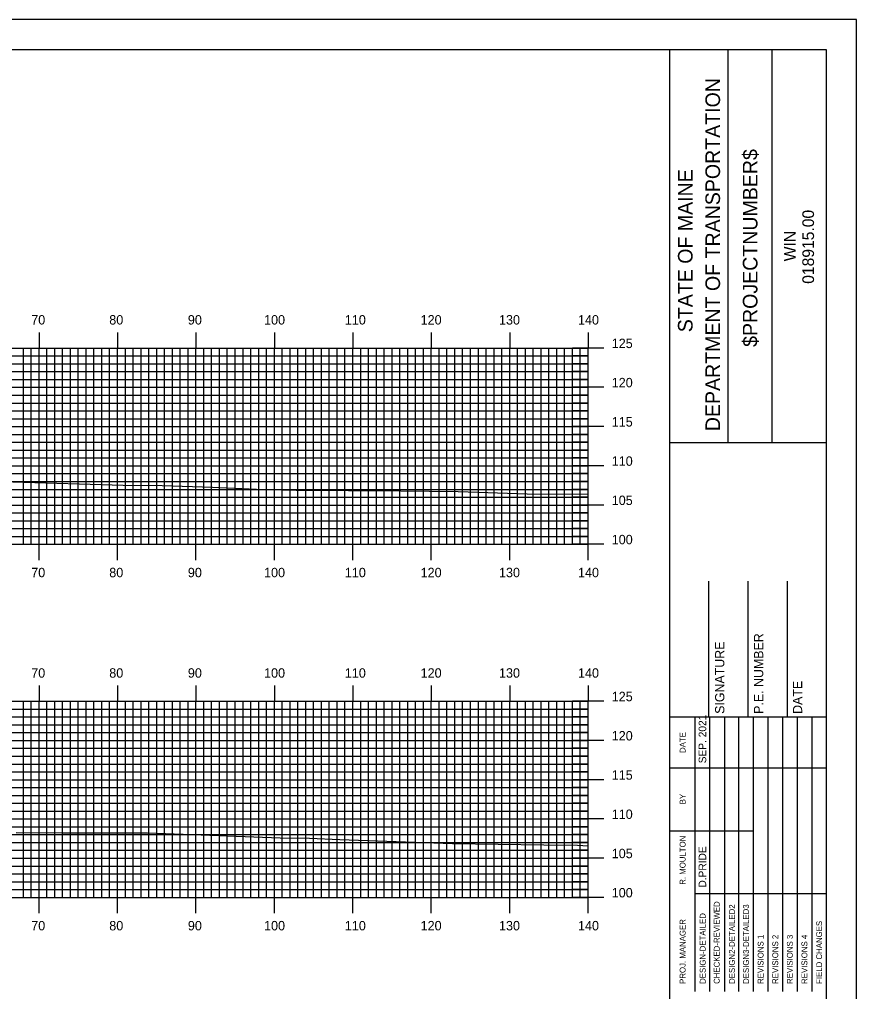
# Model space of a CAD drawing. Extents: x 1772809 to 1773153, y 442591 to 442811.
# Drawn here: x 1773042.6 to 1773149.3, y 442686.7 to 442810.5 of the extents above; entities that cross this region are included whole.
import ezdxf

# ---------------------------------------------------------------- set-up
doc = ezdxf.new("R2010")
doc.units = 0
for name, color, linetype in [('BORDER', 7, 'Continuous'), ('H_V ANNOTATION', 7, 'Continuous'), ('MAJOR', 7, 'Continuous'), ('MINOR', 7, 'Continuous'), ('PLOT BOUNDARY', 7, 'Continuous'), ('S_Roadway_Centerline', 7, 'Continuous')]:
    doc.layers.add(name, color=color, linetype=linetype)

msp = doc.modelspace()

# ---------------------------------------------------------------- linework, layer by layer
at = {"layer": 'BORDER'}
for p, q in [((1773125.52, 442596.67), (1773125.52, 442806.67)), ((1773132.98, 442756.66), (1773132.98, 442806.66)), ((1773138.57, 442756.66), (1773138.57, 442806.66)), ((1773125.52, 442756.65), (1773145.52, 442756.65)), ((1773130.52, 442721.67), (1773130.52, 442738.97)), ((1773135.52, 442721.67), (1773135.52, 442738.97)), ((1773140.52, 442721.67), (1773140.52, 442738.97)), ((1773125.52, 442721.67), (1773145.52, 442721.67))]:
    msp.add_line(p, q, dxfattribs=at)
msp.add_lwpolyline([(1772825.52, 442596.67), (1773145.52, 442596.67), (1773145.52, 442806.67), (1772825.52, 442806.67)], close=True, dxfattribs=at)
for points in [[(1773128.75, 442715.17), (1773128.75, 442721.67)], [(1773130.61, 442686.68), (1773130.61, 442721.67)], [(1773132.48, 442721.67), (1773132.48, 442686.68)], [(1773134.34, 442686.68), (1773134.34, 442721.67)], [(1773136.2, 442686.68), (1773136.2, 442721.67)], [(1773138.07, 442686.68), (1773138.07, 442721.67)], [(1773139.93, 442686.68), (1773139.93, 442721.67)], [(1773141.79, 442686.68), (1773141.79, 442721.67)], [(1773143.66, 442686.68), (1773143.66, 442721.67)], [(1773128.75, 442686.68), (1773128.75, 442720.26)], [(1773125.52, 442715.17), (1773145.52, 442715.17)], [(1773125.52, 442707.17), (1773128.75, 442707.17)], [(1773128.75, 442707.17), (1773136.2, 442707.17)], [(1773128.75, 442699.17), (1773145.52, 442699.17)]]:
    msp.add_lwpolyline(points, dxfattribs=at)
at = {"layer": 'MAJOR'}
for p, q in [((1773045.12, 442770.67), (1773045.12, 442768.67)), ((1773055.12, 442770.67), (1773055.12, 442768.67)), ((1773065.12, 442770.67), (1773065.12, 442768.67)), ((1773075.12, 442770.67), (1773075.12, 442768.67)), ((1773085.12, 442770.67), (1773085.12, 442768.67)), ((1773095.12, 442770.67), (1773095.12, 442768.67)), ((1773105.12, 442770.67), (1773105.12, 442768.67)), ((1773115.12, 442770.67), (1773115.12, 442768.67)), ((1772835.12, 442768.67), (1773115.12, 442768.67)), ((1772835.12, 442768.67), (1773115.12, 442768.67)), ((1773045.12, 442743.67), (1773045.12, 442768.67)), ((1773055.12, 442743.67), (1773055.12, 442768.67)), ((1773065.12, 442743.67), (1773065.12, 442768.67)), ((1773075.12, 442743.67), (1773075.12, 442768.67)), ((1773085.12, 442743.67), (1773085.12, 442768.67)), ((1773095.12, 442743.67), (1773095.12, 442768.67)), ((1773105.12, 442743.67), (1773105.12, 442768.67)), ((1773117.12, 442768.67), (1773113.12, 442768.67)), ((1773115.12, 442743.67), (1773115.12, 442768.67)), ((1773115.12, 442743.67), (1773115.12, 442768.67)), ((1772835.12, 442763.67), (1773115.12, 442763.67)), ((1773117.12, 442763.67), (1773113.12, 442763.67)), ((1772835.12, 442758.67), (1773115.12, 442758.67)), ((1773117.12, 442758.67), (1773113.12, 442758.67)), ((1772835.12, 442753.67), (1773115.12, 442753.67)), ((1773117.12, 442753.67), (1773113.12, 442753.67)), ((1772835.12, 442748.67), (1773115.12, 442748.67)), ((1773117.12, 442748.67), (1773113.12, 442748.67)), ((1772835.12, 442743.67), (1773115.12, 442743.67)), ((1772835.12, 442743.67), (1773115.12, 442743.67)), ((1773045.12, 442741.66), (1773045.12, 442743.67)), ((1773055.12, 442741.66), (1773055.12, 442743.67)), ((1773065.12, 442741.66), (1773065.12, 442743.67)), ((1773075.12, 442741.66), (1773075.12, 442743.67)), ((1773085.12, 442741.66), (1773085.12, 442743.67)), ((1773095.12, 442741.66), (1773095.12, 442743.67)), ((1773105.12, 442741.66), (1773105.12, 442743.67)), ((1773117.12, 442743.67), (1773113.12, 442743.67)), ((1773115.12, 442741.66), (1773115.12, 442743.67)), ((1773045.12, 442725.67), (1773045.12, 442723.67)), ((1773055.12, 442725.67), (1773055.12, 442723.67)), ((1773065.12, 442725.67), (1773065.12, 442723.67)), ((1773075.12, 442725.67), (1773075.12, 442723.67)), ((1773085.12, 442725.67), (1773085.12, 442723.67)), ((1773095.12, 442725.67), (1773095.12, 442723.67)), ((1773105.12, 442725.67), (1773105.12, 442723.67)), ((1773115.12, 442725.67), (1773115.12, 442723.67)), ((1772835.12, 442723.67), (1773115.12, 442723.67)), ((1772835.12, 442723.67), (1773115.12, 442723.67)), ((1773045.12, 442698.67), (1773045.12, 442723.67)), ((1773055.12, 442698.67), (1773055.12, 442723.67)), ((1773065.12, 442698.67), (1773065.12, 442723.67)), ((1773075.12, 442698.67), (1773075.12, 442723.67)), ((1773085.12, 442698.67), (1773085.12, 442723.67)), ((1773095.12, 442698.67), (1773095.12, 442723.67)), ((1773105.12, 442698.67), (1773105.12, 442723.67)), ((1773117.12, 442723.67), (1773113.12, 442723.67)), ((1773115.12, 442698.67), (1773115.12, 442723.67)), ((1773115.12, 442698.67), (1773115.12, 442723.67)), ((1772835.12, 442718.67), (1773115.12, 442718.67)), ((1773117.12, 442718.67), (1773113.12, 442718.67)), ((1772835.12, 442713.67), (1773115.12, 442713.67)), ((1773117.12, 442713.67), (1773113.12, 442713.67)), ((1772835.12, 442708.67), (1773115.12, 442708.67)), ((1773117.12, 442708.67), (1773113.12, 442708.67)), ((1772835.12, 442703.67), (1773115.12, 442703.67)), ((1773117.12, 442703.67), (1773113.12, 442703.67)), ((1772835.12, 442698.67), (1773115.12, 442698.67)), ((1772835.12, 442698.67), (1773115.12, 442698.67)), ((1773045.12, 442696.66), (1773045.12, 442698.67)), ((1773055.12, 442696.66), (1773055.12, 442698.67)), ((1773065.12, 442696.66), (1773065.12, 442698.67)), ((1773075.12, 442696.66), (1773075.12, 442698.67)), ((1773085.12, 442696.66), (1773085.12, 442698.67)), ((1773095.12, 442696.66), (1773095.12, 442698.67)), ((1773105.12, 442696.66), (1773105.12, 442698.67)), ((1773117.12, 442698.67), (1773113.12, 442698.67)), ((1773115.12, 442696.66), (1773115.12, 442698.67))]:
    msp.add_line(p, q, dxfattribs=at)
at = {"layer": 'MINOR'}
for p, q in [((1773043.12, 442743.67), (1773043.12, 442768.67)), ((1773044.12, 442743.67), (1773044.12, 442768.67)), ((1773046.12, 442743.67), (1773046.12, 442768.67)), ((1773047.12, 442743.67), (1773047.12, 442768.67)), ((1773048.12, 442743.67), (1773048.12, 442768.67)), ((1773049.12, 442743.67), (1773049.12, 442768.67)), ((1773050.12, 442743.67), (1773050.12, 442768.67)), ((1773051.12, 442743.67), (1773051.12, 442768.67)), ((1773052.12, 442743.67), (1773052.12, 442768.67)), ((1773053.12, 442743.67), (1773053.12, 442768.67)), ((1773054.12, 442743.67), (1773054.12, 442768.67)), ((1773056.12, 442743.67), (1773056.12, 442768.67)), ((1773057.12, 442743.67), (1773057.12, 442768.67)), ((1773058.12, 442743.67), (1773058.12, 442768.67)), ((1773059.12, 442743.67), (1773059.12, 442768.67)), ((1773060.12, 442743.67), (1773060.12, 442768.67)), ((1773061.12, 442743.67), (1773061.12, 442768.67)), ((1773062.12, 442743.67), (1773062.12, 442768.67)), ((1773063.12, 442743.67), (1773063.12, 442768.67)), ((1773064.12, 442743.67), (1773064.12, 442768.67)), ((1773066.12, 442743.67), (1773066.12, 442768.67)), ((1773067.12, 442743.67), (1773067.12, 442768.67)), ((1773068.12, 442743.67), (1773068.12, 442768.67)), ((1773069.12, 442743.67), (1773069.12, 442768.67)), ((1773070.12, 442743.67), (1773070.12, 442768.67)), ((1773071.12, 442743.67), (1773071.12, 442768.67)), ((1773072.12, 442743.67), (1773072.12, 442768.67)), ((1773073.12, 442743.67), (1773073.12, 442768.67)), ((1773074.12, 442743.67), (1773074.12, 442768.67)), ((1773076.12, 442743.67), (1773076.12, 442768.67)), ((1773077.12, 442743.67), (1773077.12, 442768.67)), ((1773078.12, 442743.67), (1773078.12, 442768.67)), ((1773079.12, 442743.67), (1773079.12, 442768.67)), ((1773080.12, 442743.67), (1773080.12, 442768.67)), ((1773081.12, 442743.67), (1773081.12, 442768.67)), ((1773082.12, 442743.67), (1773082.12, 442768.67)), ((1773083.12, 442743.67), (1773083.12, 442768.67)), ((1773084.12, 442743.67), (1773084.12, 442768.67)), ((1773086.12, 442743.67), (1773086.12, 442768.67)), ((1773087.12, 442743.67), (1773087.12, 442768.67)), ((1773088.12, 442743.67), (1773088.12, 442768.67)), ((1773089.12, 442743.67), (1773089.12, 442768.67)), ((1773090.12, 442743.67), (1773090.12, 442768.67)), ((1773091.12, 442743.67), (1773091.12, 442768.67)), ((1773092.12, 442743.67), (1773092.12, 442768.67)), ((1773093.12, 442743.67), (1773093.12, 442768.67)), ((1773094.12, 442743.67), (1773094.12, 442768.67)), ((1773096.12, 442743.67), (1773096.12, 442768.67)), ((1773097.12, 442743.67), (1773097.12, 442768.67)), ((1773098.12, 442743.67), (1773098.12, 442768.67)), ((1773099.12, 442743.67), (1773099.12, 442768.67)), ((1773100.12, 442743.67), (1773100.12, 442768.67)), ((1773101.12, 442743.67), (1773101.12, 442768.67)), ((1773102.12, 442743.67), (1773102.12, 442768.67)), ((1773103.12, 442743.67), (1773103.12, 442768.67)), ((1773104.12, 442743.67), (1773104.12, 442768.67)), ((1773106.12, 442743.67), (1773106.12, 442768.67)), ((1773107.12, 442743.67), (1773107.12, 442768.67)), ((1773108.12, 442743.67), (1773108.12, 442768.67)), ((1773109.12, 442743.67), (1773109.12, 442768.67)), ((1773110.12, 442743.67), (1773110.12, 442768.67)), ((1773111.12, 442743.67), (1773111.12, 442768.67)), ((1773112.12, 442743.67), (1773112.12, 442768.67)), ((1773113.12, 442743.67), (1773113.12, 442768.67)), ((1773114.12, 442743.67), (1773114.12, 442768.67)), ((1772835.12, 442767.67), (1773115.12, 442767.67)), ((1773115.12, 442767.67), (1773113.12, 442767.67)), ((1772835.12, 442766.67), (1773115.12, 442766.67)), ((1773115.12, 442766.67), (1773113.12, 442766.67)), ((1772835.12, 442765.67), (1773115.12, 442765.67)), ((1773115.12, 442765.67), (1773113.12, 442765.67)), ((1772835.12, 442764.67), (1773115.12, 442764.67)), ((1773115.12, 442764.67), (1773113.12, 442764.67)), ((1772835.12, 442762.67), (1773115.12, 442762.67)), ((1773115.12, 442762.67), (1773113.12, 442762.67)), ((1772835.12, 442761.67), (1773115.12, 442761.67)), ((1773115.12, 442761.67), (1773113.12, 442761.67)), ((1772835.12, 442760.67), (1773115.12, 442760.67)), ((1773115.12, 442760.67), (1773113.12, 442760.67)), ((1772835.12, 442759.67), (1773115.12, 442759.67)), ((1773115.12, 442759.67), (1773113.12, 442759.67)), ((1772835.12, 442757.67), (1773115.12, 442757.67)), ((1773115.12, 442757.67), (1773113.12, 442757.67)), ((1772835.12, 442756.67), (1773115.12, 442756.67)), ((1773115.12, 442756.67), (1773113.12, 442756.67)), ((1772835.12, 442755.67), (1773115.12, 442755.67)), ((1773115.12, 442755.67), (1773113.12, 442755.67)), ((1772835.12, 442754.67), (1773115.12, 442754.67)), ((1773115.12, 442754.67), (1773113.12, 442754.67)), ((1772835.12, 442752.67), (1773115.12, 442752.67)), ((1773115.12, 442752.67), (1773113.12, 442752.67)), ((1772835.12, 442751.67), (1773115.12, 442751.67)), ((1773115.12, 442751.67), (1773113.12, 442751.67)), ((1772835.12, 442750.67), (1773115.12, 442750.67)), ((1773115.12, 442750.67), (1773113.12, 442750.67)), ((1772835.12, 442749.67), (1773115.12, 442749.67)), ((1773115.12, 442749.67), (1773113.12, 442749.67)), ((1772835.12, 442747.67), (1773115.12, 442747.67)), ((1773115.12, 442747.67), (1773113.12, 442747.67)), ((1772835.12, 442746.67), (1773115.12, 442746.67)), ((1773115.12, 442746.67), (1773113.12, 442746.67)), ((1772835.12, 442745.67), (1773115.12, 442745.67)), ((1773115.12, 442745.67), (1773113.12, 442745.67)), ((1772835.12, 442744.67), (1773115.12, 442744.67)), ((1773115.12, 442744.67), (1773113.12, 442744.67)), ((1773043.12, 442698.67), (1773043.12, 442723.67)), ((1773044.12, 442698.67), (1773044.12, 442723.67)), ((1773046.12, 442698.67), (1773046.12, 442723.67)), ((1773047.12, 442698.67), (1773047.12, 442723.67)), ((1773048.12, 442698.67), (1773048.12, 442723.67)), ((1773049.12, 442698.67), (1773049.12, 442723.67)), ((1773050.12, 442698.67), (1773050.12, 442723.67)), ((1773051.12, 442698.67), (1773051.12, 442723.67)), ((1773052.12, 442698.67), (1773052.12, 442723.67)), ((1773053.12, 442698.67), (1773053.12, 442723.67)), ((1773054.12, 442698.67), (1773054.12, 442723.67)), ((1773056.12, 442698.67), (1773056.12, 442723.67)), ((1773057.12, 442698.67), (1773057.12, 442723.67)), ((1773058.12, 442698.67), (1773058.12, 442723.67)), ((1773059.12, 442698.67), (1773059.12, 442723.67)), ((1773060.12, 442698.67), (1773060.12, 442723.67)), ((1773061.12, 442698.67), (1773061.12, 442723.67)), ((1773062.12, 442698.67), (1773062.12, 442723.67)), ((1773063.12, 442698.67), (1773063.12, 442723.67)), ((1773064.12, 442698.67), (1773064.12, 442723.67)), ((1773066.12, 442698.67), (1773066.12, 442723.67)), ((1773067.12, 442698.67), (1773067.12, 442723.67)), ((1773068.12, 442698.67), (1773068.12, 442723.67)), ((1773069.12, 442698.67), (1773069.12, 442723.67)), ((1773070.12, 442698.67), (1773070.12, 442723.67)), ((1773071.12, 442698.67), (1773071.12, 442723.67)), ((1773072.12, 442698.67), (1773072.12, 442723.67)), ((1773073.12, 442698.67), (1773073.12, 442723.67)), ((1773074.12, 442698.67), (1773074.12, 442723.67)), ((1773076.12, 442698.67), (1773076.12, 442723.67)), ((1773077.12, 442698.67), (1773077.12, 442723.67)), ((1773078.12, 442698.67), (1773078.12, 442723.67)), ((1773079.12, 442698.67), (1773079.12, 442723.67)), ((1773080.12, 442698.67), (1773080.12, 442723.67)), ((1773081.12, 442698.67), (1773081.12, 442723.67)), ((1773082.12, 442698.67), (1773082.12, 442723.67)), ((1773083.12, 442698.67), (1773083.12, 442723.67)), ((1773084.12, 442698.67), (1773084.12, 442723.67)), ((1773086.12, 442698.67), (1773086.12, 442723.67)), ((1773087.12, 442698.67), (1773087.12, 442723.67)), ((1773088.12, 442698.67), (1773088.12, 442723.67)), ((1773089.12, 442698.67), (1773089.12, 442723.67)), ((1773090.12, 442698.67), (1773090.12, 442723.67)), ((1773091.12, 442698.67), (1773091.12, 442723.67)), ((1773092.12, 442698.67), (1773092.12, 442723.67)), ((1773093.12, 442698.67), (1773093.12, 442723.67)), ((1773094.12, 442698.67), (1773094.12, 442723.67)), ((1773096.12, 442698.67), (1773096.12, 442723.67)), ((1773097.12, 442698.67), (1773097.12, 442723.67)), ((1773098.12, 442698.67), (1773098.12, 442723.67)), ((1773099.12, 442698.67), (1773099.12, 442723.67)), ((1773100.12, 442698.67), (1773100.12, 442723.67)), ((1773101.12, 442698.67), (1773101.12, 442723.67)), ((1773102.12, 442698.67), (1773102.12, 442723.67)), ((1773103.12, 442698.67), (1773103.12, 442723.67)), ((1773104.12, 442698.67), (1773104.12, 442723.67)), ((1773106.12, 442698.67), (1773106.12, 442723.67)), ((1773107.12, 442698.67), (1773107.12, 442723.67)), ((1773108.12, 442698.67), (1773108.12, 442723.67)), ((1773109.12, 442698.67), (1773109.12, 442723.67)), ((1773110.12, 442698.67), (1773110.12, 442723.67)), ((1773111.12, 442698.67), (1773111.12, 442723.67)), ((1773112.12, 442698.67), (1773112.12, 442723.67)), ((1773113.12, 442698.67), (1773113.12, 442723.67)), ((1773114.12, 442698.67), (1773114.12, 442723.67)), ((1772835.12, 442722.67), (1773115.12, 442722.67)), ((1772835.12, 442721.67), (1773115.12, 442721.67)), ((1773115.12, 442722.67), (1773113.12, 442722.67)), ((1773115.12, 442721.67), (1773113.12, 442721.67)), ((1772835.12, 442720.67), (1773115.12, 442720.67)), ((1773115.12, 442720.67), (1773113.12, 442720.67)), ((1772835.12, 442719.67), (1773115.12, 442719.67)), ((1773115.12, 442719.67), (1773113.12, 442719.67)), ((1772835.12, 442717.67), (1773115.12, 442717.67)), ((1772835.12, 442716.67), (1773115.12, 442716.67)), ((1773115.12, 442717.67), (1773113.12, 442717.67)), ((1773115.12, 442716.67), (1773113.12, 442716.67)), ((1772835.12, 442715.67), (1773115.12, 442715.67)), ((1773115.12, 442715.67), (1773113.12, 442715.67)), ((1772835.12, 442714.67), (1773115.12, 442714.67)), ((1773115.12, 442714.67), (1773113.12, 442714.67)), ((1772835.12, 442712.67), (1773115.12, 442712.67)), ((1772835.12, 442711.67), (1773115.12, 442711.67)), ((1773115.12, 442712.67), (1773113.12, 442712.67)), ((1773115.12, 442711.67), (1773113.12, 442711.67)), ((1772835.12, 442710.67), (1773115.12, 442710.67)), ((1773115.12, 442710.67), (1773113.12, 442710.67)), ((1772835.12, 442709.67), (1773115.12, 442709.67)), ((1773115.12, 442709.67), (1773113.12, 442709.67)), ((1772835.12, 442707.67), (1773115.12, 442707.67)), ((1772835.12, 442706.67), (1773115.12, 442706.67)), ((1773115.12, 442707.67), (1773113.12, 442707.67)), ((1773115.12, 442706.67), (1773113.12, 442706.67)), ((1772835.12, 442705.67), (1773115.12, 442705.67)), ((1773115.12, 442705.67), (1773113.12, 442705.67)), ((1772835.12, 442704.67), (1773115.12, 442704.67)), ((1773115.12, 442704.67), (1773113.12, 442704.67)), ((1772835.12, 442702.67), (1773115.12, 442702.67)), ((1772835.12, 442701.67), (1773115.12, 442701.67)), ((1773115.12, 442702.67), (1773113.12, 442702.67)), ((1773115.12, 442701.67), (1773113.12, 442701.67)), ((1772835.12, 442700.67), (1773115.12, 442700.67)), ((1773115.12, 442700.67), (1773113.12, 442700.67)), ((1772835.12, 442699.67), (1773115.12, 442699.67)), ((1773115.12, 442699.67), (1773113.12, 442699.67))]:
    msp.add_line(p, q, dxfattribs=at)
at = {"layer": 'PLOT BOUNDARY'}
msp.add_lwpolyline([(1772809.33, 442590.55), (1773149.33, 442590.55), (1773149.33, 442810.55), (1772809.33, 442810.55)], close=True, dxfattribs=at)
at = {"layer": 'S_Roadway_Centerline'}
for points in [[(1773041.77, 442751.61), (1773055.86, 442751.19), (1773060.81, 442751.18), (1773067.24, 442750.96), (1773072.84, 442750.68), (1773077.89, 442750.57), (1773091.24, 442750.47), (1773098.55, 442750.41), (1773107.35, 442750.1), (1773115.12, 442750.04)], [(1773042.22, 442706.93), (1773048.14, 442706.88), (1773058.96, 442706.92), (1773065.79, 442706.64), (1773075.84, 442706.28), (1773079.6, 442706.23), (1773083.47, 442706.05), (1773097.83, 442705.52), (1773109.48, 442705.37), (1773113.76, 442705.31), (1773115.12, 442705.26)]]:
    msp.add_lwpolyline(points, dxfattribs=at)

# ---------------------------------------------------------------- texts
at = {"layer": 'BORDER'}
for s, height, p in [('DEPARTMENT OF TRANSPORTATION', 1.8635, (1773131.93, 442758.08)), ('$PROJECTNUMBER$', 1.8635, (1773136.7, 442768.82)), ('STATE OF MAINE', 1.8635, (1773128.43, 442770.69)), ('018915.00', 1.491, (1773143.91, 442776.86)), ('WIN', 1.491, (1773141.59, 442779.73)), ('P.E. NUMBER', 1.1811, (1773137.44, 442722.06)), ('SIGNATURE', 1.181, (1773132.48, 442722.06)), ('DATE', 1.181, (1773142.4, 442722.06)), ('SEP. 2021', 0.969, (1773130.17, 442715.76)), ('DATE', 0.743, (1773127.53, 442717.08)), ('BY', 0.743, (1773127.53, 442710.54)), ('R. MOULTON', 0.745, (1773127.53, 442700.28)), ('D.PRIDE', 0.969, (1773130.17, 442699.92)), ('CHECKED-REVIEWED', 0.7455, (1773131.88, 442687.65)), ('DESIGN2-DETAILED2', 0.7455, (1773133.82, 442687.65)), ('DESIGN3-DETAILED3', 0.7455, (1773135.61, 442687.65)), ('PROJ. MANAGER', 0.7455, (1773127.53, 442687.65)), ('DESIGN-DETAILED', 0.7455, (1773130.09, 442687.65)), ('FIELD CHANGES', 0.7455, (1773144.93, 442687.65)), ('REVISIONS 1', 0.7455, (1773137.47, 442687.65)), ('REVISIONS 2', 0.7455, (1773139.34, 442687.65)), ('REVISIONS 3', 0.7455, (1773141.2, 442687.65)), ('REVISIONS 4', 0.7455, (1773143.06, 442687.65))]:
    msp.add_text(s, height=height, rotation=90, dxfattribs=at).set_placement(p)
at = {"layer": 'H_V ANNOTATION'}
for s, p in [('70', (1773044.12, 442771.67)), ('80', (1773054.07, 442771.67)), ('90', (1773064.09, 442771.67)), ('100', (1773073.8, 442771.67)), ('110', (1773084.1, 442771.67)), ('120', (1773093.76, 442771.67)), ('130', (1773103.75, 442771.67)), ('140', (1773113.82, 442771.67)), ('125', (1773118.12, 442768.67)), ('120', (1773118.12, 442763.67)), ('115', (1773118.12, 442758.67)), ('110', (1773118.12, 442753.67)), ('105', (1773118.12, 442748.67)), ('100', (1773118.12, 442743.67)), ('70', (1773044.12, 442739.47)), ('80', (1773054.07, 442739.47)), ('90', (1773064.09, 442739.47)), ('100', (1773073.8, 442739.47)), ('110', (1773084.1, 442739.47)), ('120', (1773093.76, 442739.47)), ('130', (1773103.75, 442739.47)), ('140', (1773113.82, 442739.47)), ('70', (1773044.12, 442726.67)), ('80', (1773054.07, 442726.67)), ('90', (1773064.09, 442726.67)), ('100', (1773073.8, 442726.67)), ('110', (1773084.1, 442726.67)), ('120', (1773093.76, 442726.67)), ('130', (1773103.75, 442726.67)), ('140', (1773113.82, 442726.67)), ('125', (1773118.12, 442723.67)), ('120', (1773118.12, 442718.67)), ('115', (1773118.12, 442713.67)), ('110', (1773118.12, 442708.67)), ('105', (1773118.12, 442703.67)), ('100', (1773118.12, 442698.67)), ('70', (1773044.12, 442694.47)), ('80', (1773054.07, 442694.47)), ('90', (1773064.09, 442694.47)), ('100', (1773073.8, 442694.47)), ('110', (1773084.1, 442694.47)), ('120', (1773093.76, 442694.47)), ('130', (1773103.75, 442694.47)), ('140', (1773113.82, 442694.47))]:
    msp.add_text(s, height=1.2, dxfattribs=at).set_placement(p)

doc.saveas('drawing.dxf')
